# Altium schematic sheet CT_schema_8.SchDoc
size 147 x 119 mm
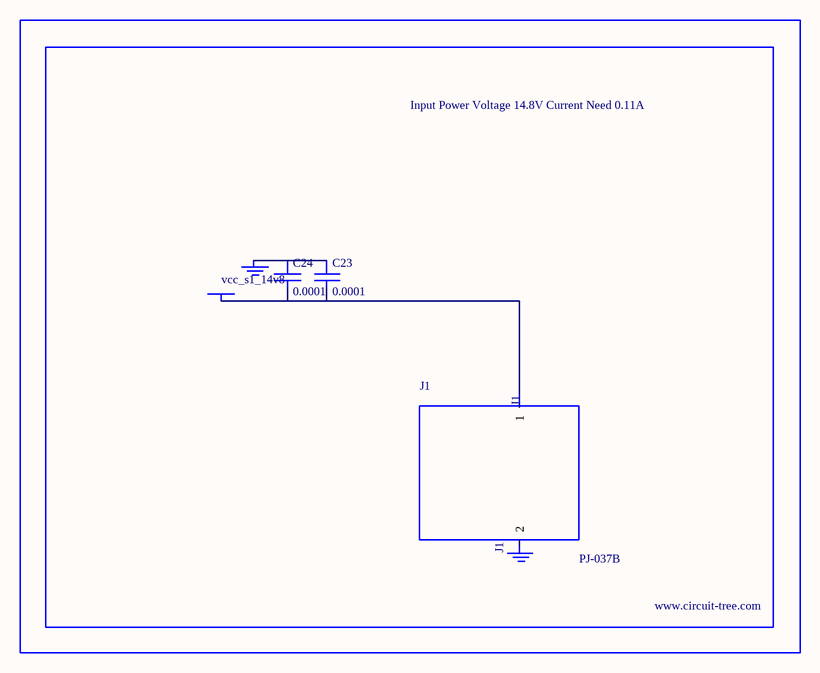
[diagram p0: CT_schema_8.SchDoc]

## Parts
BORDER7  (no value)
C23  0.0001  [EXV-9H]
C24  0.0001  [EXV-9H]
GND_INSTANCE_7_0  (no value)
GND_INSTANCE_7_1  (no value)
J1  PJ-037B  [PJ-037B_PACKAGE]
POWER_INSTANCE_7_0  vcc_s1_14v8

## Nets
NetC23_1: C23.1 C24.1 GND_INSTANCE_7_0.0(GND)
NetC23_2: C23.2 C24.2 J1.1 POWER_INSTANCE_7_0.0(PWR)

Not connected (* = marked no-connect by the designer): GND_INSTANCE_7_1 0(GND); J1 2

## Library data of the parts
BORDER7 = BORDER_PAGE7
C23 C24 = EDK107M035A9HAA
GND_INSTANCE_7_0 GND_INSTANCE_7_1 = GND
POWER_INSTANCE_7_0 = PWR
